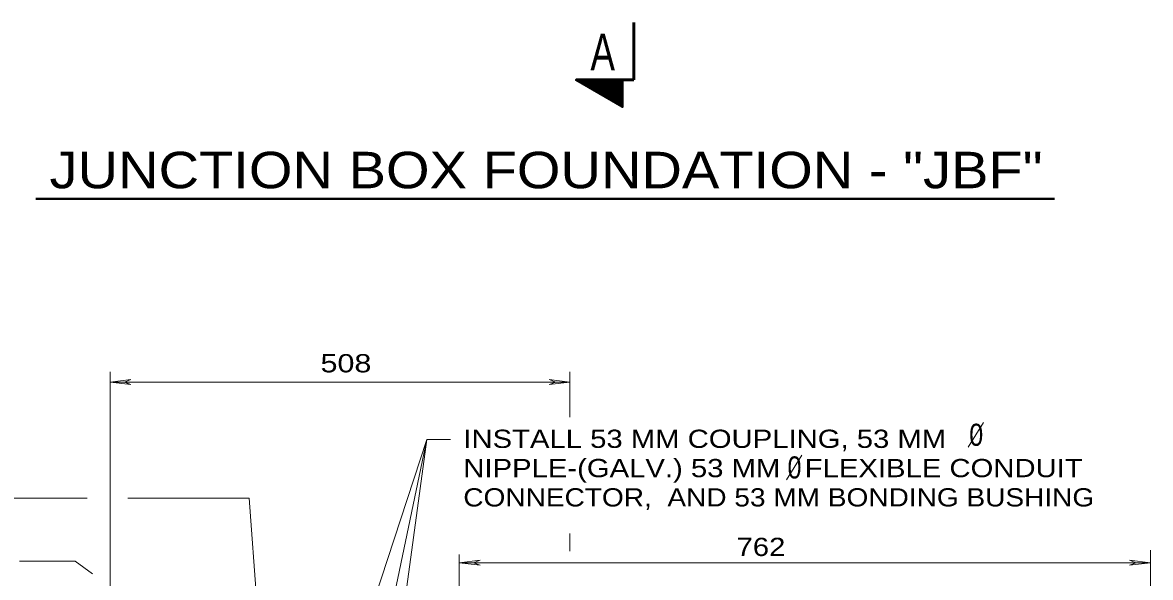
# Model space of a CAD drawing. Extents: x 312583 to 312853, y 144419 to 144586.
# Drawn here: x 312640.66 to 312687.67, y 144500.1 to 144523.22 of the extents above; entities that cross this region are included whole.
import ezdxf
from ezdxf.enums import TextEntityAlignment as Align

# ---------------------------------------------------------------- set-up
doc = ezdxf.new("R2010")
doc.units = 0
doc.header["$LTSCALE"] = 0.3
doc.layers.add('1', color=7, linetype='Continuous', lineweight=40)
doc.layers.add('2', color=7, linetype='Continuous', lineweight=13)

msp = doc.modelspace()

# ---------------------------------------------------------------- linework, layer by layer
at = {"layer": '1', "lineweight": 53}
for p in [(312666.1335, 144523.2159), (312665.6581, 144520.8239)]:
    msp.add_line(p, (312666.1335, 144520.8239), dxfattribs=at)
at = {"layer": '1', "lineweight": 35}
for p, q in [((312663.7568, 144520.8239), (312663.7568, 144520.8086)), ((312663.7875, 144520.8239), (312663.7798, 144520.8009)), ((312663.8181, 144520.8239), (312663.7951, 144520.7856)), ((312663.8411, 144520.8239), (312663.8181, 144520.7779)), ((312663.8718, 144520.8239), (312663.8411, 144520.7626)), ((312663.8948, 144520.8239), (312663.8565, 144520.7549)), ((312663.9255, 144520.8239), (312663.8795, 144520.7396)), ((312663.9561, 144520.8239), (312663.9025, 144520.7319)), ((312663.9868, 144520.8239), (312663.9178, 144520.7166)), ((312664.0098, 144520.8239), (312663.9408, 144520.7089)), ((312664.0328, 144520.8239), (312663.9638, 144520.6936)), ((312664.0635, 144520.8239), (312663.9868, 144520.6859)), ((312664.0865, 144520.8239), (312664.0021, 144520.6706)), ((312664.1171, 144520.8239), (312664.0251, 144520.6553)), ((312664.1478, 144520.8239), (312664.0481, 144520.6476)), ((312664.1785, 144520.8239), (312664.0635, 144520.6323)), ((312664.2015, 144520.8239), (312664.0865, 144520.6169)), ((312664.2321, 144520.8239), (312664.1095, 144520.6093)), ((312664.2551, 144520.8239), (312664.1248, 144520.5939)), ((312664.2858, 144520.8239), (312664.1478, 144520.5863)), ((312664.3165, 144520.8239), (312664.1708, 144520.5709)), ((312664.3395, 144520.8239), (312664.1861, 144520.5633)), ((312664.3701, 144520.8239), (312664.2168, 144520.5479)), ((312664.3931, 144520.8239), (312664.2321, 144520.5403)), ((312664.4238, 144520.8239), (312664.2551, 144520.5249)), ((312664.4545, 144520.8239), (312664.2781, 144520.5173)), ((312664.4775, 144520.8239), (312664.2935, 144520.5019)), ((312664.5081, 144520.8239), (312664.3165, 144520.4943)), ((312664.5311, 144520.8239), (312664.3395, 144520.4789)), ((312664.5618, 144520.8239), (312664.3548, 144520.4636)), ((312664.5848, 144520.8239), (312664.3778, 144520.4559)), ((312664.6155, 144520.8239), (312664.4008, 144520.4406)), ((312664.6461, 144520.8239), (312664.4161, 144520.4253)), ((312664.6768, 144520.8239), (312664.4391, 144520.4176)), ((312664.6998, 144520.8239), (312664.4621, 144520.4023)), ((312664.7228, 144520.8239), (312664.4851, 144520.3946)), ((312664.7535, 144520.8239), (312664.5005, 144520.3793)), ((312664.7841, 144520.8239), (312664.5235, 144520.3716)), ((312664.8071, 144520.8239), (312664.5465, 144520.3563)), ((312664.8378, 144520.8239), (312664.5618, 144520.3486)), ((312664.8685, 144520.8239), (312664.5848, 144520.3333)), ((312664.8915, 144520.8239), (312664.6078, 144520.3256)), ((312664.9221, 144520.8239), (312664.6231, 144520.3103)), ((312664.9528, 144520.8239), (312664.6461, 144520.3026)), ((312664.9758, 144520.8239), (312664.6691, 144520.2873)), ((312665.0065, 144520.8163), (312664.6845, 144520.2719)), ((312665.0295, 144520.8239), (312664.7151, 144520.2643)), ((312665.0601, 144520.8239), (312664.7305, 144520.2489)), ((312665.0831, 144520.8239), (312664.7535, 144520.2413)), ((312665.1138, 144520.8239), (312664.7765, 144520.2259)), ((312665.1445, 144520.8239), (312664.7918, 144520.2183)), ((312665.1751, 144520.8239), (312664.8148, 144520.2029)), ((312665.1981, 144520.8239), (312664.8378, 144520.1953)), ((312665.2211, 144520.8239), (312664.8531, 144520.1799)), ((312665.2518, 144520.8163), (312664.8761, 144520.1723)), ((312665.2825, 144520.8239), (312664.8991, 144520.1569)), ((312665.3055, 144520.8239), (312664.9145, 144520.1493)), ((312665.3361, 144520.8239), (312664.9375, 144520.1339)), ((312665.3668, 144520.8239), (312664.9605, 144520.1186)), ((312665.3898, 144520.8239), (312664.9835, 144520.1109)), ((312665.4205, 144520.8239), (312664.9988, 144520.0956)), ((312665.4511, 144520.8239), (312665.0218, 144520.0803)), ((312665.4741, 144520.8163), (312665.0448, 144520.0726)), ((312665.5048, 144520.8163), (312665.0601, 144520.0573)), ((312665.5278, 144520.8239), (312665.0831, 144520.0496)), ((312665.5585, 144520.8239), (312665.1061, 144520.0343)), ((312665.5815, 144520.8239), (312665.1215, 144520.0266)), ((312665.6121, 144520.8239), (312665.1445, 144520.0113)), ((312665.6428, 144520.8239), (312665.1675, 144520.0036)), ((312665.6581, 144520.8009), (312665.1828, 144519.9883)), ((312665.6581, 144520.7473), (312665.2135, 144519.9806)), ((312665.6581, 144520.7089), (312665.2288, 144519.9653)), ((312665.6581, 144520.6553), (312665.2518, 144519.9576)), ((312665.6581, 144520.6093), (312665.2748, 144519.9423)), ((312665.6581, 144520.5633), (312665.2901, 144519.9269)), ((312665.6581, 144520.5173), (312665.3131, 144519.9193)), ((312665.6581, 144520.4636), (312665.3361, 144519.9039)), ((312665.6581, 144520.4176), (312665.3515, 144519.8886)), ((312665.6581, 144520.3716), (312665.3745, 144519.8809)), ((312665.6581, 144520.3179), (312665.3898, 144519.8656)), ((312665.6581, 144520.2719), (312665.4128, 144519.8579)), ((312665.6581, 144520.2259), (312665.4358, 144519.8426)), ((312665.6581, 144520.1723), (312665.4511, 144519.8349)), ((312665.6581, 144520.1263), (312665.4818, 144519.8196)), ((312665.6581, 144520.0803), (312665.4971, 144519.8119)), ((312665.6581, 144520.0343), (312665.5201, 144519.7966)), ((312665.6581, 144519.9806), (312665.5431, 144519.7889)), ((312665.6581, 144519.9423), (312665.5585, 144519.7736)), ((312665.6581, 144519.8886), (312665.5815, 144519.7659)), ((312665.6581, 144519.8426), (312665.6045, 144519.7506)), ((312665.6581, 144519.7889), (312665.6198, 144519.7353)), ((312665.6581, 144519.7429), (312665.6428, 144519.7276))]:
    msp.add_line(p, q, dxfattribs=at)
at = {"layer": '1', "lineweight": 53}
msp.add_lwpolyline([(312665.6581, 144520.8239), (312665.6581, 144519.7123), (312663.7415, 144520.8239)], close=True, dxfattribs=at)
at = {"layer": '2', "lineweight": 40}
msp.add_line((312641.2134, 144515.8789), (312683.6714, 144515.8789), dxfattribs=at)
at = {"layer": '2'}
for p, q in [((312644.3122, 144493.9266), (312644.3122, 144508.6696)), ((312663.4789, 144506.7759), (312663.4789, 144508.6696)), ((312644.3122, 144508.2403), (312645.1785, 144508.3476)), ((312644.3122, 144508.2403), (312663.4789, 144508.2403)), ((312644.3122, 144508.2403), (312645.1785, 144508.1329)), ((312645.1785, 144508.3476), (312644.9025, 144508.2403)), ((312645.1785, 144508.1329), (312644.9025, 144508.2403)), ((312662.6125, 144508.3476), (312662.8885, 144508.2403)), ((312663.4789, 144508.2403), (312662.6125, 144508.3476)), ((312662.6125, 144508.1329), (312662.8885, 144508.2403)), ((312663.4789, 144508.2403), (312662.6125, 144508.1329)), ((312680.0833, 144505.5286), (312680.7197, 144506.5559)), ((312672.5081, 144504.1674), (312673.1445, 144505.1871)), ((312639.6739, 144503.4026), (312643.3539, 144503.4026)), ((312645.0482, 144503.4026), (312650.1082, 144503.4026)), ((312650.1082, 144503.4026), (312651.3272, 144486.6816)), ((312663.4789, 144501.1946), (312663.4789, 144501.9306)), ((312658.8635, 144497.6986), (312658.8635, 144501.0566)), ((312687.6749, 144492.1863), (312687.6749, 144501.2329)), ((312642.8479, 144500.7806), (312640.5259, 144500.7806)), ((312643.5762, 144500.2439), (312642.8479, 144500.7806)), ((312658.8635, 144500.7116), (312659.7299, 144500.8189)), ((312658.8635, 144500.7116), (312687.6749, 144500.7116)), ((312658.8635, 144500.7116), (312659.7299, 144500.6043)), ((312659.7299, 144500.8189), (312659.4539, 144500.7116)), ((312659.7299, 144500.6043), (312659.4539, 144500.7116)), ((312686.8085, 144500.8189), (312687.0845, 144500.7116)), ((312687.6749, 144500.7116), (312686.8085, 144500.8189)), ((312686.8085, 144500.6043), (312687.0845, 144500.7116)), ((312687.6749, 144500.7116), (312686.8085, 144500.6043))]:
    msp.add_line(p, q, dxfattribs=at)
for points in [[(312658.5032, 144505.8483), (312657.5142, 144505.8483), (312654.2405, 144495.8893)], [(312654.9689, 144493.6889), (312657.5142, 144505.8483), (312655.3292, 144489.8249)]]:
    msp.add_lwpolyline(points, dxfattribs=at)

# ---------------------------------------------------------------- texts
at = {"layer": '1', "width": 0.75}
msp.add_text('A', height=1.533, dxfattribs=at).set_placement((312664.8416, 144521.2226), align=Align.CENTER)
at = {"layer": '2'}
for s, height, width, p in [('JUNCTION BOX FOUNDATION - "JBF"', 1.52, 1.15, (312662.482, 144516.312)), ('0', 0.92, 0.85, (312680.413, 144505.5822)), ('0', 0.92, 0.85, (312672.8378, 144504.2211))]:
    msp.add_text(s, height=height, dxfattribs=dict(at, width=width)).set_placement(p, align=Align.CENTER)
for s, width, p in [('508 ', 1.25, (312653.0797, 144508.6419)), ('INSTALL 53 MM COUPLING, 53 MM', 1.2, (312659.0322, 144505.4946)), ('NIPPLE-(GALV.) 53 MM   FLEXIBLE CONDUIT', 1.2, (312659.0322, 144504.2746)), ('CONNECTOR,  AND 53 MM BONDING BUSHING', 1.15, (312659.0322, 144503.0546)), ('762 ', 1.2, (312670.4218, 144500.9905))]:
    msp.add_text(s, height=0.76, dxfattribs=dict(at, width=width)).set_placement(p)

doc.saveas('drawing.dxf')
